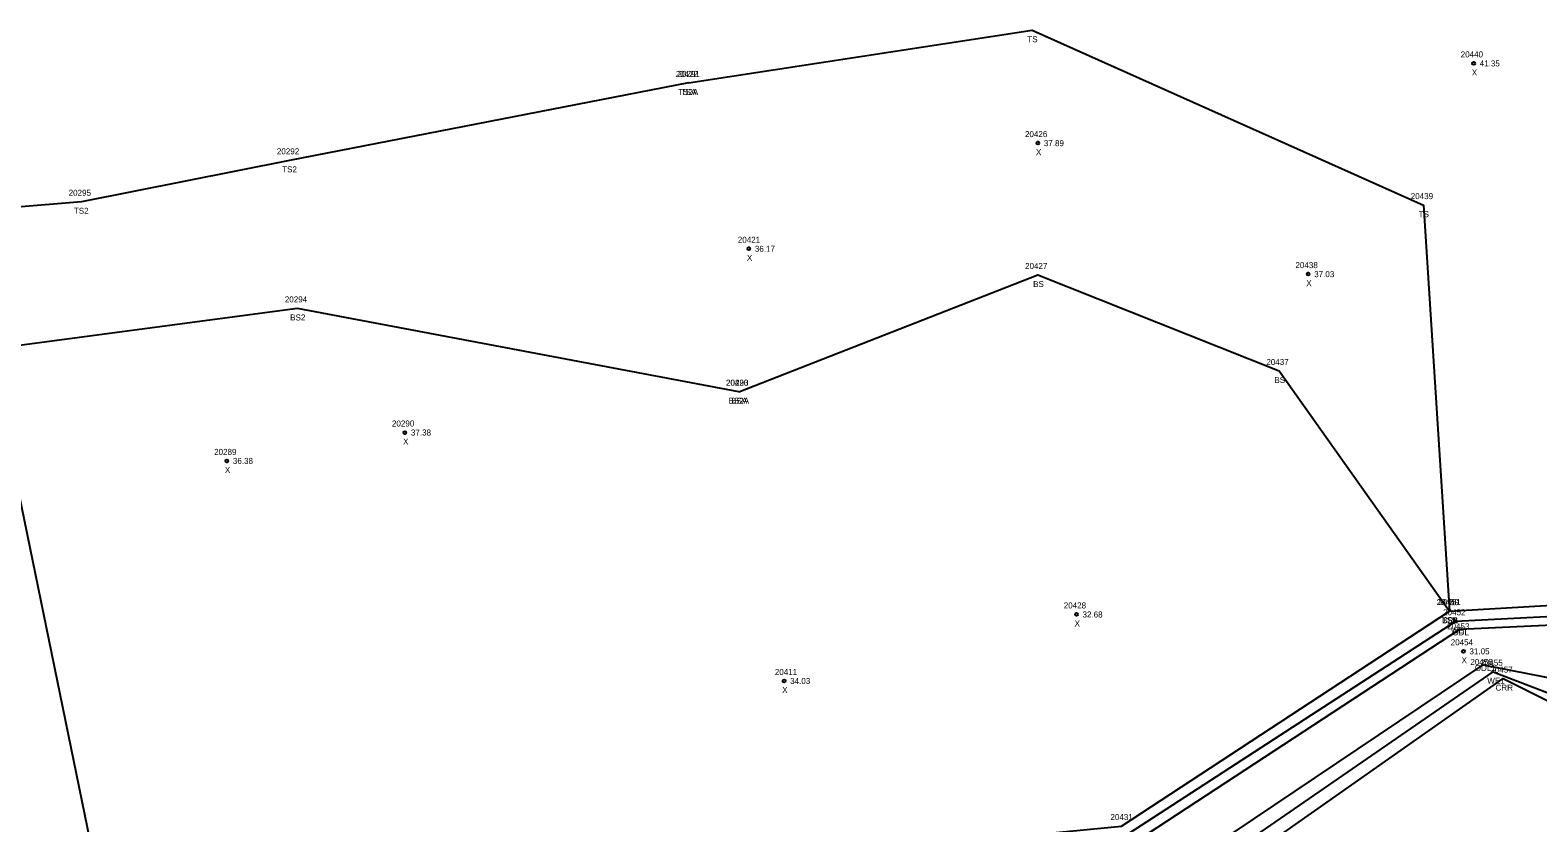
# Model space of a CAD drawing. Extents: x 2445178 to 2446260, y 791158 to 792318.
# Drawn here: x 2445746.6 to 2445997.4, y 791938.1 to 792069.9 of the extents above; entities that cross this region are included whole.
import ezdxf

# ---------------------------------------------------------------- set-up
doc = ezdxf.new("R2010")
doc.units = 0
for name, color, linetype in [('RD_DTM_BkLn2', 7, 'Continuous'), ('RD_EX_H2O', 7, 'Continuous'), ('RD_EX_H2O_txCode', 7, 'Continuous'), ('RD_Sketch8', 7, 'Continuous'), ('RD_SMD_Locator', 7, 'Continuous'), ('RD_SMD_Misc', 7, 'Continuous')]:
    doc.layers.add(name, color=color, linetype=linetype)

msp = doc.modelspace()

# ---------------------------------------------------------------- linework, layer by layer
at = {"layer": 'RD_DTM_BkLn2'}
for points in [[(2445856.1, 792061.09), (2445913.26, 792069.86), (2445978.36, 792040.77), (2445982.7, 791973.27)], [(2445856.1, 792061.09), (2445789.75, 792048.22), (2445755.11, 792041.33), (2445731.65, 792039.36), (2445734.09, 792026.35)], [(2445864.47, 792009.75), (2445914.21, 792029.16), (2445954.34, 792013.2), (2445982.7, 791973.27)], [(2445864.47, 792009.75), (2445791.07, 792023.6), (2445740.15, 792016.85)], [(2445721.97, 791816.74), (2445749.98, 791821.69), (2445763.92, 791830.66), (2445773.82, 791855.25), (2445775.82, 791885.45), (2445758.38, 791926.24), (2445744.75, 791992.74), (2445740.15, 792016.85)]]:
    msp.add_lwpolyline(points, dxfattribs=at)
at = {"layer": 'RD_EX_H2O'}
for points in [[(2445749.98, 791821.69), (2445784.5, 791816.33), (2445784.5, 791816.33), (2445826.97, 791831.85), (2445864.4, 791840.41), (2445865.35, 791848.28), (2445857.59, 791890.6), (2445862.25, 791903.98), (2445902.88, 791935.07), (2445928.13, 791937.54), (2445982.7, 791973.27), (2446006.36, 791974.66), (2446055.29, 791944.59), (2446112.86, 791944.82), (2446116.06, 791949.26), (2446125.53, 791975.87), (2446156.76, 791972.15), (2446187.24, 792018.21)], [(2445757.3, 791817.48), (2445784.85, 791815.29), (2445827.3, 791828.95), (2445865.88, 791838.48), (2445867.77, 791849.3), (2445858.86, 791890.39), (2445863.96, 791902.52), (2445903.58, 791933.29), (2445928.32, 791935.62), (2445983.75, 791971.59), (2446005.28, 791972.74), (2446055.03, 791943.12), (2446113.69, 791943.23), (2446117.06, 791949.31), (2446126.55, 791974.16), (2446158.67, 791970.49), (2446188.67, 792015.57)], [(2445756.08, 791812.92), (2445785.69, 791811.94), (2445827.07, 791827.18), (2445867.4, 791836.35), (2445869.07, 791850.26), (2445862.28, 791889.54), (2445866.87, 791900.55), (2445904.83, 791930.74), (2445929.24, 791934.15), (2445984.41, 791970.25), (2446004.58, 791971.21), (2446054.77, 791941.67), (2446115.62, 791938.17), (2446120.64, 791945.97), (2446127.84, 791972.01), (2446160.1, 791969.34), (2446190.11, 792012.94)], [(2445748.32, 791780.49), (2445788.24, 791788.44), (2445846, 791811.01), (2445891.85, 791826.96), (2445872.2, 791885.31), (2445911.58, 791917.24), (2445942.41, 791930.41), (2445989.95, 791963.2), (2446004.43, 791957.67), (2446037.13, 791928.19), (2446062.94, 791924.63), (2446122.42, 791925.89), (2446133.98, 791956.62), (2446163.05, 791958.48), (2446202.11, 792005.16)], [(2445752.43, 791785.31), (2445788.27, 791790.61), (2445845.46, 791813.31), (2445889.72, 791828.98), (2445868.44, 791886.37), (2445910.27, 791920.69), (2445939.62, 791931.64), (2445988.31, 791964.33), (2446005.31, 791961.03), (2446034.89, 791932.66), (2446061.86, 791927.42), (2446120.16, 791928.99), (2446131.56, 791958.98), (2446161.23, 791962.03), (2446198.32, 792006.02)], [(2445746.88, 791778.25), (2445790.91, 791782.86), (2445846.87, 791809.11), (2445896.01, 791824.25), (2445877, 791883.78), (2445912.26, 791916.16), (2445942.78, 791927.77), (2445991.6, 791962.06), (2446003.69, 791956.06), (2446036.32, 791927.07), (2446060.96, 791923.67), (2446122.97, 791923.97), (2446134.24, 791956.18), (2446163.21, 791958.01), (2446202.51, 792004.24)]]:
    msp.add_lwpolyline(points, dxfattribs=at)
at = {"layer": 'RD_SMD_Locator'}
for centre, radius in [((2445913.26, 792069.86), 0.001), ((2445986.71, 792064.33), 0.25), ((2445856.1, 792061.09), 0.001), ((2445856.1, 792061.09), 0.001), ((2445914.21, 792051.08), 0.25), ((2445789.75, 792048.22), 0.001), ((2445755.11, 792041.33), 0.001), ((2445978.36, 792040.77), 0.001), ((2445866.14, 792033.51), 0.25), ((2445914.21, 792029.16), 0.001), ((2445959.18, 792029.3), 0.25), ((2445791.07, 792023.6), 0.001), ((2445954.34, 792013.2), 0.001), ((2445864.47, 792009.75), 0.001), ((2445864.47, 792009.75), 0.001), ((2445808.93, 792002.97), 0.25), ((2445779.31, 791998.25), 0.25), ((2445920.64, 791972.72), 0.25), ((2445982.7, 791973.27), 0.001), ((2445982.7, 791973.27), 0.001), ((2445982.7, 791973.27), 0.001), ((2445983.75, 791971.59), 0.001), ((2445984.41, 791970.25), 0.001), ((2445985.01, 791966.6), 0.25), ((2445988.31, 791964.33), 0.001), ((2445989.95, 791963.2), 0.001), ((2445872.01, 791961.67), 0.25), ((2445991.6, 791962.06), 0.001)]:
    msp.add_circle(centre, radius, dxfattribs=at)

# ---------------------------------------------------------------- texts
at = {"layer": 'RD_EX_H2O_txCode'}
for s, p in [('20449', (2445980.58, 791974.27)), ('20452', (2445981.63, 791972.59)), ('CRL', (2445981.47, 791971.27)), ('20453', (2445982.29, 791970.25)), ('WE', (2445982.91, 791969.59)), ('ODL', (2445983.17, 791969.25)), ('20456', (2445986.16, 791964.33)), ('20455', (2445987.83, 791964.2)), ('ODL1', (2445986.9, 791963.33)), ('20457', (2445989.48, 791963.06)), ('WE1', (2445988.97, 791961.2)), ('CRR', (2445990.35, 791960.06)), ('20431', (2445926.29, 791938.54))]:
    msp.add_text(s, height=1, dxfattribs=at).set_placement(p)
at = {"layer": 'RD_Sketch8'}
for s, p in [('20440', (2445984.55, 792065.33)), ('X', (2445986.4, 792062.33)), ('41.35', (2445987.71, 792063.83)), ('20426', (2445912.07, 792052.08)), ('37.89', (2445915.21, 792050.58)), ('X', (2445913.9, 792049.08)), ('20421', (2445864.3, 792034.51)), ('36.17', (2445867.14, 792033.01)), ('X', (2445865.82, 792031.51)), ('20438', (2445957.06, 792030.3)), ('X', (2445958.87, 792027.3)), ('37.03', (2445960.18, 792028.8)), ('20290', (2445806.77, 792003.97)), ('37.38', (2445809.93, 792002.47)), ('20289', (2445777.19, 791999.25)), ('X', (2445808.62, 792000.97)), ('36.38', (2445780.31, 791997.75)), ('X', (2445778.99, 791996.25)), ('20428', (2445918.52, 791973.72)), ('32.68', (2445921.64, 791972.22)), ('X', (2445920.33, 791970.72)), ('20454', (2445982.89, 791967.6)), ('X', (2445984.7, 791964.6)), ('31.05', (2445986.01, 791966.1)), ('20411', (2445870.46, 791962.67)), ('X', (2445871.69, 791959.67)), ('34.03', (2445873.01, 791961.17))]:
    msp.add_text(s, height=1, dxfattribs=at).set_placement(p)
at = {"layer": 'RD_SMD_Misc'}
for s, p in [('TS', (2445912.46, 792067.86)), ('20422', (2445853.98, 792062.09)), ('20291', (2445854.26, 792062.09)), ('TS2A', (2445854.37, 792059.09)), ('TSA', (2445854.82, 792059.09)), ('20292', (2445787.63, 792049.22)), ('TS2', (2445788.51, 792046.22)), ('20295', (2445752.99, 792042.33)), ('20439', (2445976.24, 792041.77)), ('TS2', (2445753.86, 792039.33)), ('TS', (2445977.56, 792038.77)), ('20427', (2445912.09, 792030.16)), ('BS', (2445913.43, 792027.16)), ('20294', (2445788.95, 792024.6)), ('BS2', (2445789.84, 792021.6)), ('20437', (2445952.22, 792014.2)), ('20420', (2445862.32, 792010.75)), ('20293', (2445862.35, 792010.75)), ('BS', (2445953.56, 792011.2)), ('BS2A', (2445862.76, 792007.75)), ('BSA', (2445863.2, 792007.75)), ('20450', (2445980.54, 791974.27)), ('20451', (2445980.86, 791974.27)), ('TSB', (2445981.43, 791971.27)), ('BSB', (2445981.45, 791971.27))]:
    msp.add_text(s, height=1, dxfattribs=at).set_placement(p)

doc.saveas('drawing.dxf')
